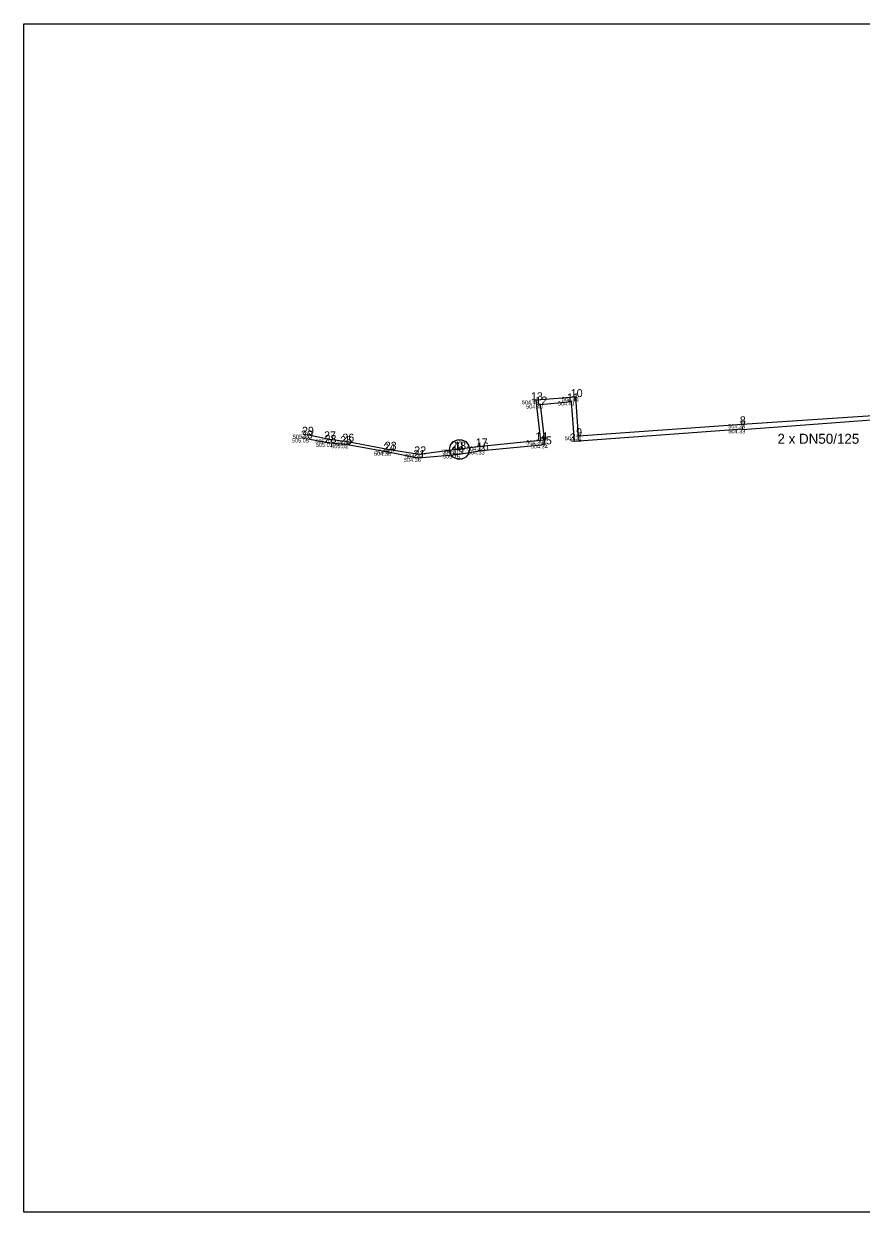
# Model space of a CAD drawing. Extents: x -873642.4 to -873558.4, y -1012603.5 to -1012544.1.
# Drawn here: x -873642.4 to -873600.6, y -1012603.5 to -1012544.1 of the extents above; entities that cross this region are included whole.
import ezdxf

# ---------------------------------------------------------------- set-up
doc = ezdxf.new("R2010")
doc.units = 0
for name, color, linetype in [('Měřený bod', 7, 'Continuous'), ('revizní šachta', 7, 'Continuous'), ('rám', 7, 'Continuous'), ('teplovod', 7, 'Continuous'), ('teplovod-stávající', 7, 'Continuous'), ('Výška měřeného bodu', 7, 'Continuous'), ('Číslo měřeného bodu', 7, 'Continuous')]:
    doc.layers.add(name, color=color, linetype=linetype)

msp = doc.modelspace()

# ---------------------------------------------------------------- linework, layer by layer
at = {"layer": 'Měřený bod'}
for p, q in [((-873616.845, -1012562.879), (-873616.845, -1012562.879)), ((-873616.619, -1012563.09), (-873616.619, -1012563.09)), ((-873615.056, -1012562.939), (-873615.056, -1012562.939)), ((-873614.845, -1012562.721), (-873614.845, -1012562.721)), ((-873606.523, -1012564.081), (-873606.523, -1012564.081)), ((-873606.513, -1012564.331), (-873606.513, -1012564.331)), ((-873628.33, -1012564.789), (-873628.33, -1012564.789)), ((-873628.33, -1012564.789), (-873628.33, -1012564.789)), ((-873628.286, -1012564.602), (-873628.286, -1012564.602)), ((-873628.286, -1012564.602), (-873628.286, -1012564.602)), ((-873627.175, -1012564.831), (-873627.175, -1012564.831)), ((-873627.156, -1012565.008), (-873627.156, -1012565.008)), ((-873626.267, -1012564.948), (-873626.267, -1012564.948)), ((-873616.617, -1012564.885), (-873616.617, -1012564.885)), ((-873614.917, -1012564.94), (-873614.917, -1012564.94)), ((-873614.709, -1012564.674), (-873614.709, -1012564.674)), ((-873626.37, -1012565.074), (-873626.37, -1012565.074)), ((-873624.225, -1012565.448), (-873624.225, -1012565.448)), ((-873624.155, -1012565.35), (-873624.155, -1012565.35)), ((-873622.675, -1012565.585), (-873622.675, -1012565.585)), ((-873620.816, -1012565.342), (-873620.816, -1012565.342)), ((-873620.781, -1012565.588), (-873620.781, -1012565.588)), ((-873620.781, -1012565.588), (-873620.781, -1012565.588)), ((-873620.674, -1012565.349), (-873620.674, -1012565.349)), ((-873620.674, -1012565.349), (-873620.674, -1012565.349)), ((-873619.591, -1012565.185), (-873619.591, -1012565.185)), ((-873619.546, -1012565.389), (-873619.546, -1012565.389)), ((-873616.386, -1012565.084), (-873616.386, -1012565.084)), ((-873622.734, -1012565.761), (-873622.734, -1012565.761))]:
    msp.add_line(p, q, dxfattribs=at)
at = {"layer": 'revizní šachta'}
for p, q in [((-873621.109, -1012565.12), (-873620.971, -1012564.946)), ((-873620.971, -1012564.946), (-873620.77, -1012564.849)), ((-873620.77, -1012564.849), (-873620.547, -1012564.849)), ((-873620.547, -1012564.849), (-873620.347, -1012564.946)), ((-873620.347, -1012564.946), (-873620.208, -1012565.12)), ((-873621.159, -1012565.337), (-873621.109, -1012565.12)), ((-873621.109, -1012565.554), (-873621.159, -1012565.337)), ((-873620.971, -1012565.728), (-873621.109, -1012565.554)), ((-873620.208, -1012565.554), (-873620.347, -1012565.728)), ((-873620.208, -1012565.12), (-873620.159, -1012565.337)), ((-873620.159, -1012565.337), (-873620.208, -1012565.554)), ((-873620.77, -1012565.824), (-873620.971, -1012565.728)), ((-873620.547, -1012565.824), (-873620.77, -1012565.824)), ((-873620.347, -1012565.728), (-873620.547, -1012565.824))]:
    msp.add_line(p, q, dxfattribs=at)
at = {"layer": 'rám'}
msp.add_lwpolyline([(-873642.449, -1012603.46), (-873642.449, -1012544.06), (-873558.449, -1012544.06), (-873558.449, -1012603.46)], close=True, dxfattribs=at)
at = {"layer": 'teplovod'}
for p, q in [((-873614.917, -1012564.94), (-873615.056, -1012562.939)), ((-873606.505, -1012564.33), (-873614.917, -1012564.94))]:
    msp.add_line(p, q, dxfattribs=at)
for points in [[(-873585.514, -1012565.613), (-873585.76, -1012562.556), (-873594.984, -1012563.323), (-873606.523, -1012564.081), (-873614.709, -1012564.674), (-873614.845, -1012562.721), (-873616.845, -1012562.879), (-873616.617, -1012564.885), (-873619.591, -1012565.185), (-873620.816, -1012565.342), (-873622.675, -1012565.585), (-873624.155, -1012565.35), (-873626.267, -1012564.948), (-873627.175, -1012564.831)], [(-873627.156, -1012565.008), (-873626.37, -1012565.074), (-873624.225, -1012565.448), (-873622.734, -1012565.761), (-873620.781, -1012565.588), (-873619.546, -1012565.389), (-873616.386, -1012565.084), (-873616.619, -1012563.09), (-873615.056, -1012562.939)], [(-873606.513, -1012564.331), (-873594.957, -1012563.474), (-873586.039, -1012562.797), (-873585.815, -1012565.648)]]:
    msp.add_lwpolyline(points, dxfattribs=at)
at = {"layer": 'teplovod-stávající'}
for p, q in [((-873628.33, -1012564.789), (-873627.156, -1012565.008)), ((-873627.175, -1012564.831), (-873628.286, -1012564.602))]:
    msp.add_line(p, q, dxfattribs=at)

# ---------------------------------------------------------------- texts
at = {"layer": 'teplovod'}
msp.add_text('2 x DN50/125', height=0.5, dxfattribs=at).set_placement((-873604.762, -1012565.052))
at = {"layer": 'Výška měřeného bodu'}
for s, p in [('504.42', (-873617.549, -1012563.079)), ('504.40', (-873617.33, -1012563.29)), ('504.41', (-873615.745, -1012563.139)), ('504.43', (-873615.547, -1012562.921)), ('504.33', (-873607.225, -1012564.281)), ('504.33', (-873607.215, -1012564.531)), ('505.05', (-873629.041, -1012564.989)), ('505.05', (-873629.041, -1012564.989)), ('505.07', (-873628.999, -1012564.802)), ('505.07', (-873628.999, -1012564.802)), ('505.01', (-873627.864, -1012565.031)), ('505.01', (-873627.845, -1012565.208)), ('505.04', (-873626.973, -1012565.148)), ('504.35', (-873617.328, -1012565.085)), ('504.31', (-873615.398, -1012564.874)), ('505.02', (-873627.074, -1012565.274)), ('504.38', (-873624.933, -1012565.648)), ('504.39', (-873624.862, -1012565.55)), ('504.36', (-873623.383, -1012565.785)), ('504.37', (-873621.529, -1012565.542)), ('505.16', (-873621.489, -1012565.788)), ('505.16', (-873621.489, -1012565.788)), ('505.15', (-873621.385, -1012565.549)), ('505.15', (-873621.385, -1012565.549)), ('504.32', (-873620.295, -1012565.385)), ('504.33', (-873620.248, -1012565.589)), ('504.34', (-873617.092, -1012565.284)), ('504.36', (-873623.442, -1012565.961))]:
    msp.add_text(s, height=0.2, dxfattribs=at).set_placement(p)
at = {"layer": 'Číslo měřeného bodu'}
for s, p in [('13', (-873617.091, -1012562.879)), ('12', (-873616.867, -1012563.09)), ('11', (-873615.289, -1012562.939)), ('10', (-873615.1, -1012562.721)), ('8', (-873606.645, -1012564.081)), ('30', (-873628.585, -1012564.789)), ('30', (-873628.585, -1012564.789)), ('29', (-873628.537, -1012564.602)), ('29', (-873628.537, -1012564.602)), ('27', (-873627.432, -1012564.831)), ('9', (-873614.83, -1012564.674)), ('7', (-873606.64, -1012564.331)), ('28', (-873627.408, -1012565.008)), ('25', (-873626.625, -1012565.074)), ('26', (-873626.519, -1012564.948)), ('24', (-873624.475, -1012565.448)), ('23', (-873624.401, -1012565.35)), ('20', (-873621.071, -1012565.342)), ('18', (-873620.926, -1012565.349)), ('18', (-873620.926, -1012565.349)), ('17', (-873619.848, -1012565.185)), ('16', (-873619.798, -1012565.389)), ('14', (-873616.867, -1012564.885)), ('15', (-873616.641, -1012565.084)), ('31', (-873615.15, -1012564.94)), ('21', (-873622.967, -1012565.761)), ('22', (-873622.923, -1012565.585)), ('19', (-873621.032, -1012565.588)), ('19', (-873621.032, -1012565.588))]:
    msp.add_text(s, height=0.4, dxfattribs=at).set_placement(p)

doc.saveas('drawing.dxf')
